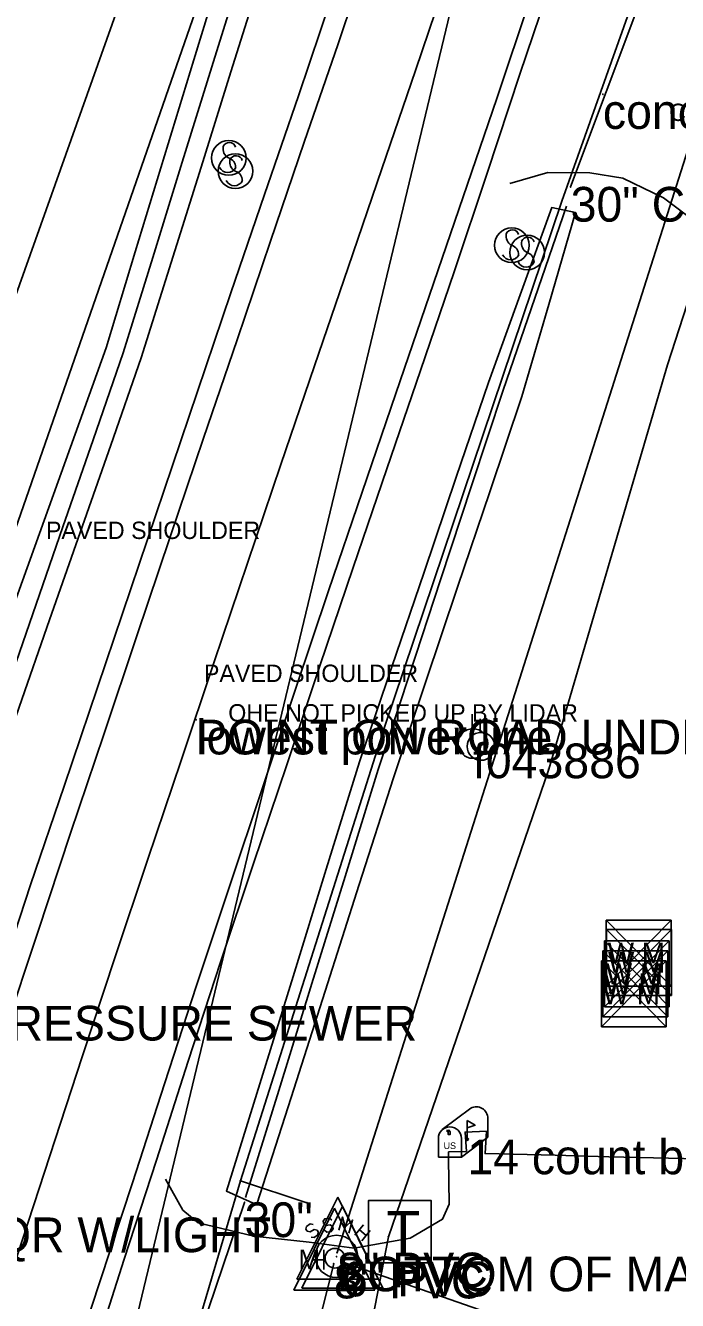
# Model space of a CAD drawing. Extents: x 1802180 to 1804859, y 572524 to 575172.
# Drawn here: x 1803260.9 to 1803354.8, y 573167.1 to 573350.8 of the extents above; entities that cross this region are included whole.
import ezdxf

# ---------------------------------------------------------------- set-up
doc = ezdxf.new("R2010")
doc.units = 0
for name, color, linetype in [('EX_EDGE_PAVEMENT', 7, 'Continuous'), ('EX_SHOULDER', 7, 'Continuous'), ('S_BASELINE', 7, 'Continuous'), ('S_CAL_CORNER', 7, 'Continuous'), ('S_DITCHLINE', 7, 'Continuous'), ('S_DRG_PT_SYM', 7, 'Continuous'), ('S_ELECTRIC_UTILITIES_ANNOT', 7, 'Continuous'), ('S_GAS_UTILITIES', 7, 'Continuous'), ('S_MAILBOX', 7, 'Continuous'), ('S_MAILBOX_ANNOT', 7, 'Continuous'), ('S_MANHOLE', 7, 'Continuous'), ('S_MANHOLE_ANNOT', 7, 'Continuous'), ('S_MISC_BOUNDARY', 7, 'Continuous'), ('S_MSC_PT_SYM', 7, 'Continuous'), ('S_PARKING', 7, 'Continuous'), ('S_PARKING_ANNOT', 7, 'Continuous'), ('S_PAVEMENT_CROWN', 7, 'Continuous'), ('S_SANITARY_SEWER', 7, 'Continuous'), ('S_SANITARY_SEWER_ANNOT', 7, 'Continuous'), ('S_SHOULDER_ANNOT', 7, 'Continuous'), ('S_SIDE_DRAIN', 7, 'Continuous'), ('S_SIDE_DRAIN_ANNOT', 7, 'Continuous'), ('S_SIGN', 7, 'Continuous'), ('S_SURVEY_TEXT', 7, 'Continuous'), ('S_SURVEY_TEXT_ANNOT', 7, 'Continuous'), ('S_TELEPHONE_UTILITIES', 7, 'Continuous'), ('S_UTILITY_POLE', 7, 'Continuous'), ('S_UTILITY_POLE_ANNOT', 7, 'Continuous'), ('S_UTL_PT_SYM', 7, 'Continuous'), ('S_WATER_UTILITIES', 7, 'Continuous')]:
    doc.layers.add(name, color=color, linetype=linetype)

msp = doc.modelspace()

# ---------------------------------------------------------------- linework, layer by layer
at = {"layer": 'EX_EDGE_PAVEMENT'}
for points in [[(1803243.97, 573162.84), (1803248.63, 573177.34), (1803253.31, 573191.59), (1803257.97, 573205.83), (1803262.69, 573220.17), (1803267.44, 573234.4), (1803272.21, 573248.61), (1803276.97, 573262.83), (1803281.77, 573277.1), (1803286.59, 573291.3), (1803291.41, 573305.51), (1803296.22, 573319.72), (1803301.07, 573333.96), (1803305.94, 573348.15), (1803310.67, 573362.21)], [(1803333.6, 573354.66), (1803328.79, 573340.27), (1803323.93, 573326.08), (1803319.1, 573311.94), (1803314.25, 573297.74), (1803309.42, 573283.54), (1803304.58, 573269.34), (1803299.82, 573255.17), (1803295.08, 573240.94), (1803290.3, 573226.71), (1803285.55, 573212.49), (1803280.96, 573198.31), (1803276.36, 573184.02), (1803271.65, 573169.78), (1803267.02, 573155.77)]]:
    msp.add_lwpolyline(points, dxfattribs=at)
at = {"layer": 'EX_SHOULDER'}
for points in [[(1803244.54, 573072.71), (1803248.63, 573087.13), (1803252.74, 573101.56), (1803256.68, 573116.02), (1803261.13, 573130.33), (1803265.55, 573144.67), (1803270.59, 573158.74), (1803275.14, 573173.03), (1803279.82, 573187.3), (1803284.37, 573201.59), (1803289.02, 573215.83), (1803293.78, 573230.06), (1803298.55, 573244.28), (1803303.32, 573258.5), (1803308.12, 573272.7), (1803312.96, 573286.9), (1803317.8, 573301.09), (1803322.64, 573315.29), (1803327.4, 573329.51), (1803332.12, 573343.77), (1803336.9, 573357.97)], [(1803217.45, 573083.45), (1803221.29, 573098), (1803225.36, 573112.47), (1803229.64, 573126.91), (1803234.04, 573141.25), (1803238.37, 573155.6), (1803242.85, 573169.96), (1803247.56, 573184.22), (1803252.29, 573198.46), (1803256.96, 573212.72), (1803261.68, 573226.97), (1803266.49, 573241.18), (1803271.3, 573255.39), (1803276.08, 573269.61), (1803280.88, 573283.83), (1803285.7, 573298.03), (1803290.52, 573312.24), (1803295.34, 573326.45), (1803300.24, 573340.63), (1803305.01, 573354.83)]]:
    msp.add_lwpolyline(points, dxfattribs=at)
at = {"layer": 'S_BASELINE'}
msp.add_line((1803248.92, 573048.02), (1803445.92, 573868.28), dxfattribs=at)
at = {"layer": 'S_CAL_CORNER'}
for p, q in [((1803305.42, 573180.37), (1803299.55, 573168.56)), ((1803305.89, 573181.96), (1803300.01, 573170.14)), ((1803306.6, 573180.67), (1803300.72, 573168.85)), ((1803305.42, 573180.37), (1803311.23, 573168.56)), ((1803305.89, 573181.96), (1803311.7, 573170.14)), ((1803306.6, 573180.67), (1803312.41, 573168.85)), ((1803300.01, 573170.14), (1803311.7, 573170.14)), ((1803299.55, 573168.56), (1803311.23, 573168.56)), ((1803300.72, 573168.85), (1803312.41, 573168.85))]:
    msp.add_line(p, q, dxfattribs=at)
at = {"layer": 'S_DITCHLINE'}
for points in [[(1803289.39, 573359.67), (1803285.18, 573345.84), (1803280.96, 573332.01), (1803276.75, 573318.18), (1803272.53, 573304.35), (1803268.08, 573291.91), (1803263.63, 573279.47), (1803259.18, 573267.02), (1803254.72, 573254.58), (1803250.18, 573241.12), (1803245.65, 573227.66), (1803241.11, 573214.21), (1803236.57, 573200.75), (1803232.01, 573188.55), (1803227.46, 573176.35), (1803222.91, 573164.14), (1803218.36, 573151.94), (1803215.97, 573139.2), (1803213.59, 573126.47), (1803211.2, 573113.73), (1803208.82, 573100.99)], [(1803292.03, 573358.57), (1803287.77, 573344.83), (1803283.51, 573331.09), (1803279.25, 573317.35), (1803274.99, 573303.61), (1803270.66, 573291.08), (1803266.33, 573278.54), (1803262, 573266.01), (1803257.67, 573253.48), (1803253.07, 573240.14), (1803248.46, 573226.8), (1803243.85, 573213.46), (1803239.24, 573200.12), (1803234.76, 573187.94), (1803230.29, 573175.75), (1803225.81, 573163.57)], [(1803294.83, 573357.82), (1803290.52, 573344.09), (1803286.21, 573330.36), (1803281.9, 573316.63), (1803277.59, 573302.9), (1803273.2, 573290.32), (1803268.8, 573277.73), (1803264.41, 573265.15), (1803260.01, 573252.56), (1803255.39, 573239.11), (1803250.78, 573225.66), (1803246.16, 573212.21), (1803241.54, 573198.76), (1803237.14, 573186.74), (1803232.74, 573174.73), (1803228.35, 573162.72), (1803223.95, 573150.71), (1803220.17, 573138.28), (1803216.38, 573125.85), (1803212.6, 573113.42), (1803208.82, 573100.99)], [(1803294.14, 573180.94), (1803289.87, 573182.85), (1803294.67, 573198.31), (1803299.46, 573213.78), (1803304.25, 573229.24), (1803309.04, 573244.7), (1803313.68, 573258.36), (1803318.32, 573272.03), (1803322.96, 573285.7), (1803327.6, 573299.36), (1803332.16, 573311.95), (1803336.72, 573324.54), (1803340.13, 573323.82), (1803336.27, 573310.57), (1803332.41, 573297.33), (1803327.79, 573283.59), (1803323.16, 573269.85), (1803318.54, 573256.12), (1803313.92, 573242.38), (1803309, 573227.02), (1803304.08, 573211.67), (1803299.17, 573196.32), (1803294.25, 573180.96)], [(1803292.63, 573181.91), (1803297.4, 573197.34), (1803302.17, 573212.76), (1803306.94, 573228.19), (1803311.71, 573243.61), (1803316.21, 573257.27), (1803320.7, 573270.93), (1803325.19, 573284.59), (1803329.69, 573298.25), (1803334.26, 573311.49), (1803338.83, 573324.73)]]:
    msp.add_lwpolyline(points, dxfattribs=at)
at = {"layer": 'S_DRG_PT_SYM'}
for points in [[(1803339.43, 573327.52), (1803339.43, 573327.57), (1803339.43, 573327.52), (1803339.38, 573327.52), (1803339.43, 573327.52), (1803339.43, 573327.47), (1803339.43, 573327.52), (1803339.48, 573327.52)], [(1803292.48, 573181.22), (1803292.48, 573181.27), (1803292.48, 573181.22), (1803292.43, 573181.22), (1803292.48, 573181.22), (1803292.48, 573181.17), (1803292.48, 573181.22), (1803292.53, 573181.22)]]:
    msp.add_lwpolyline(points, dxfattribs=at)
at = {"layer": 'S_GAS_UTILITIES'}
for p, q in [((1803338.18, 573325.46), (1803351.16, 573362.17)), ((1803312.58, 573249.52), (1803338.18, 573325.46)), ((1803291.88, 573184.33), (1803312.58, 573249.52)), ((1803282.01, 573151.05), (1803291.88, 573184.33)), ((1803291.88, 573184.33), (1803301.46, 573181.17))]:
    msp.add_line(p, q, dxfattribs=at)
at = {"layer": 'S_MAILBOX'}
for p, q in [((1803320.93, 573191.71), (1803325.07, 573194.82)), ((1803327.5, 573193.34), (1803327.5, 573190.63)), ((1803324.55, 573193), (1803324.55, 573190.28)), ((1803320.38, 573190.43), (1803320.38, 573187.72)), ((1803323.7, 573187.72), (1803327.5, 573190.63)), ((1803323.7, 573190.43), (1803323.7, 573187.72)), ((1803320.38, 573187.72), (1803323.7, 573187.72))]:
    msp.add_line(p, q, dxfattribs=at)
for points in [[(1803321.56, 573191.55), (1803321.79, 573191.41), (1803321.79, 573191.02), (1803322.09, 573191.02), (1803322.09, 573191.38), (1803321.9, 573191.63), (1803321.56, 573191.58)], [(1803324.55, 573193), (1803325.66, 573192.33), (1803324.55, 573191.98)]]:
    msp.add_lwpolyline(points, dxfattribs=at)
for centre, end in [((1803325.84, 573193.34), 117.5718), ((1803322.04, 573190.43), 180)]:
    msp.add_arc(centre, 1.66, 0, end, dxfattribs=at)
msp.add_ellipse((1803324.55, 573190.28), major_axis=(0.145, 0.132), ratio=0.564646, dxfattribs=at)
at = {"layer": 'S_MANHOLE'}
for p, q in [((1803303.91, 573171.57), (1803303.91, 573174.4)), ((1803302.33, 573172.97), (1803303.91, 573172.97))]:
    msp.add_line(p, q, dxfattribs=at)
msp.add_circle((1803305.49, 573173.18), 1.42, dxfattribs=at)
at = {"layer": 'S_MISC_BOUNDARY'}
msp.add_lwpolyline([(1802880.88, 573735.6), (1803051.71, 573733.48), (1803213.27, 573730.83), (1803216.46, 573532.09), (1803301.63, 573530.07), (1803296.75, 573432.28), (1803274.96, 573355.36), (1803226.68, 573219.53), (1803202.19, 573137.5), (1803157.77, 572977.33), (1803158.5, 572726.69), (1802889.88, 572728.1)], dxfattribs=at)
at = {"layer": 'S_MSC_PT_SYM'}
for points in [[(1803344.07, 573340.88), (1803344.07, 573340.93), (1803344.07, 573340.88), (1803344.02, 573340.88), (1803344.07, 573340.88), (1803344.07, 573340.83), (1803344.07, 573340.88), (1803344.12, 573340.88)], [(1803285.51, 573250.76), (1803285.51, 573250.81), (1803285.51, 573250.76), (1803285.46, 573250.76), (1803285.51, 573250.76), (1803285.51, 573250.71), (1803285.51, 573250.76), (1803285.56, 573250.76)]]:
    msp.add_lwpolyline(points, dxfattribs=at)
at = {"layer": 'S_PARKING'}
for points in [[(1803330.66, 573328), (1803336.13, 573329.59), (1803342.17, 573329.57), (1803346.94, 573328.79), (1803352.78, 573325.97), (1803358.03, 573322.02), (1803360.17, 573317.79), (1803360.25, 573312.38), (1803359.47, 573303.06), (1803363.42, 573302.55), (1803374.67, 573302.5), (1803389.66, 573302.32), (1803393.51, 573302.29), (1803394.36, 573302.26), (1803394.42, 573298.33)], [(1803330.66, 573328), (1803336.13, 573329.59), (1803342.17, 573329.57), (1803346.94, 573328.79), (1803352.78, 573325.97), (1803358.03, 573322.02), (1803360.17, 573317.79), (1803360.25, 573312.38), (1803359.47, 573303.06), (1803363.42, 573302.55), (1803374.67, 573302.5), (1803389.66, 573302.32), (1803393.51, 573302.29), (1803394.36, 573302.26), (1803394.42, 573298.33)], [(1803327.12, 573188.25), (1803327.29, 573191.47), (1803324.24, 573191.35), (1803324.43, 573188.57), (1803321.86, 573188.49), (1803321.82, 573187.57), (1803321.95, 573180.95), (1803320.98, 573178.8), (1803316.31, 573176.08), (1803308.26, 573174.62), (1803301.77, 573175.5), (1803293.82, 573176.37), (1803285.78, 573178.27), (1803283.61, 573180.11), (1803281.09, 573184.58)], [(1803359.95, 573187.45), (1803344.95, 573187.8), (1803337.21, 573188.04), (1803327.12, 573188.25), (1803327.29, 573191.47), (1803324.24, 573191.35), (1803324.43, 573188.57), (1803321.86, 573188.49), (1803321.82, 573187.57), (1803321.95, 573180.95), (1803320.98, 573178.8), (1803316.31, 573176.08), (1803308.26, 573174.62), (1803301.77, 573175.5), (1803293.82, 573176.37), (1803285.78, 573178.27), (1803283.61, 573180.11), (1803281.09, 573184.58)], [(1803359.95, 573187.45), (1803344.95, 573187.8), (1803337.21, 573188.04), (1803327.12, 573188.25)]]:
    msp.add_lwpolyline(points, dxfattribs=at)
at = {"layer": 'S_PAVEMENT_CROWN'}
msp.add_lwpolyline([(1803255.16, 573159.41), (1803259.77, 573173.68), (1803264.45, 573187.93), (1803269.12, 573202.19), (1803273.79, 573216.44), (1803278.57, 573230.66), (1803283.35, 573244.88), (1803288.11, 573259.1), (1803292.89, 573273.32), (1803297.72, 573287.52), (1803302.55, 573301.72), (1803307.38, 573315.92), (1803312.22, 573330.12), (1803317.11, 573344.3), (1803321.91, 573358.51)], dxfattribs=at)
at = {"layer": 'S_SANITARY_SEWER'}
for p, q in [((1803305.8, 573173.98), (1803414.87, 573517.25)), ((1803290.35, 573367.12), (1803235.59, 573209.54)), ((1803301.4, 573177.74), (1803301.32, 573177.35)), ((1803301.32, 573177.35), (1803301.51, 573177.08)), ((1803301.94, 573178.13), (1803301.4, 573177.74)), ((1803301.51, 573177.08), (1803301.94, 573176.97)), ((1803302.36, 573178.05), (1803301.94, 573178.13)), ((1803301.94, 573176.97), (1803302.48, 573177.32)), ((1803302.48, 573177.32), (1803302.95, 573177.24)), ((1803302.95, 573177.24), (1803303.1, 573176.97)), ((1803303.1, 573176.97), (1803303.02, 573176.54)), ((1803308.37, 573176.5), (1803309.61, 573177.97)), ((1803309.03, 573177.28), (1803310, 573176.46)), ((1803310.58, 573177.16), (1803309.34, 573175.69)), ((1803302.48, 573176.15), (1803302.09, 573176.23)), ((1803303.02, 573176.54), (1803302.48, 573176.15)), ((1803253.84, 572969.86), (1803305.33, 573172.39)), ((1803306.51, 573172.68), (1803354.58, 573155.92))]:
    msp.add_line(p, q, dxfattribs=at)
for points in [[(1803305.04, 573178.67), (1803304.69, 573178.94), (1803304.03, 573178.87), (1803303.8, 573178.52), (1803303.84, 573178.21), (1803304.19, 573177.9), (1803304.81, 573178.01), (1803305.19, 573177.7), (1803305.23, 573177.39), (1803304.96, 573177.01), (1803304.34, 573176.93), (1803303.99, 573177.2)], [(1803307.48, 573176.81), (1803308.02, 573178.67), (1803306.98, 573177.66), (1803306.59, 573179.1), (1803306.05, 573177.24)]]:
    msp.add_lwpolyline(points, dxfattribs=at)
msp.add_circle((1803305.72, 573173.44), 3.05, dxfattribs=at)
at = {"layer": 'S_SIDE_DRAIN'}
for p, q in [((1803339.43, 573327.52), (1803350.15, 573356.19)), ((1803282.63, 573152.15), (1803292.48, 573181.22))]:
    msp.add_line(p, q, dxfattribs=at)
at = {"layer": 'S_SIGN'}
for centre in [(1803290.2, 573331.69), (1803291.16, 573329.79), (1803330.96, 573319.11), (1803333.17, 573318.07)]:
    msp.add_circle(centre, 2.5, dxfattribs=at)
for centre, radius, start, end in [((1803290.89, 573333.02), 1.51, 167.1196, 241.9813), ((1803290.28, 573332.96), 0.952, 16.5258, 156.8957), ((1803289.79, 573330.35), 1.4, 358.6529, 73.7063), ((1803291.85, 573331.12), 1.51, 167.1196, 241.9813), ((1803291.24, 573331.06), 0.952, 16.5258, 156.8957), ((1803290.05, 573330.87), 1.28, 204.641, 335.359), ((1803290.75, 573328.45), 1.4, 358.6529, 73.7063), ((1803291.01, 573328.97), 1.28, 204.641, 335.359), ((1803331.64, 573320.44), 1.51, 167.1196, 241.9813), ((1803331.03, 573320.38), 0.952, 16.5258, 156.8957), ((1803333.25, 573319.34), 0.952, 16.5258, 156.8957), ((1803330.54, 573317.76), 1.4, 358.6529, 73.7063), ((1803333.86, 573319.4), 1.51, 167.1196, 241.9813), ((1803330.8, 573318.28), 1.28, 204.641, 335.359), ((1803333.02, 573317.24), 1.28, 204.641, 335.359), ((1803332.76, 573316.72), 1.4, 358.6529, 73.7063)]:
    msp.add_arc(centre, radius, start, end, dxfattribs=at)
at = {"layer": 'S_SURVEY_TEXT'}
msp.add_line((1803290.13, 573250.5), (1803290.13, 573250.5), dxfattribs=at)
at = {"layer": 'S_TELEPHONE_UTILITIES'}
msp.add_lwpolyline([(1803310.33, 573172.5), (1803310.33, 573181.5), (1803319.33, 573181.5), (1803319.33, 573172.5)], close=True, dxfattribs=at)
at = {"layer": 'S_UTILITY_POLE'}
for p, q in [((1803325.24, 573249.47), (1803325.24, 573251.58)), ((1803326.4, 573248.92), (1803326.4, 573250.91))]:
    msp.add_line(p, q, dxfattribs=at)
for centre, radius in [((1803325.36, 573247.33), 2.13), ((1803326.52, 573246.91), 2)]:
    msp.add_circle(centre, radius, dxfattribs=at)
at = {"layer": 'S_UTL_PT_SYM'}
for points in [[(1803338.18, 573325.46), (1803338.18, 573325.51), (1803338.18, 573325.46), (1803338.13, 573325.46), (1803338.18, 573325.46), (1803338.18, 573325.41), (1803338.18, 573325.46), (1803338.23, 573325.46)], [(1803353.38, 573301.89), (1803353.38, 573301.94), (1803353.38, 573301.89), (1803353.33, 573301.89), (1803353.38, 573301.89), (1803353.38, 573301.84), (1803353.38, 573301.89), (1803353.43, 573301.89)], [(1803285.51, 573250.76), (1803285.51, 573250.81), (1803285.51, 573250.76), (1803285.46, 573250.76), (1803285.51, 573250.76), (1803285.51, 573250.71), (1803285.51, 573250.76), (1803285.56, 573250.76)], [(1803312.58, 573249.52), (1803312.58, 573249.57), (1803312.58, 573249.52), (1803312.53, 573249.52), (1803312.58, 573249.52), (1803312.58, 573249.47), (1803312.58, 573249.52), (1803312.63, 573249.52)], [(1803336.27, 573243.65), (1803336.27, 573243.7), (1803336.27, 573243.65), (1803336.22, 573243.65), (1803336.27, 573243.65), (1803336.27, 573243.6), (1803336.27, 573243.65), (1803336.32, 573243.65)], [(1803291.88, 573184.33), (1803291.88, 573184.38), (1803291.88, 573184.33), (1803291.83, 573184.33), (1803291.88, 573184.33), (1803291.88, 573184.28), (1803291.88, 573184.33), (1803291.93, 573184.33)], [(1803291.88, 573184.33), (1803291.88, 573184.38), (1803291.88, 573184.33), (1803291.83, 573184.33), (1803291.88, 573184.33), (1803291.88, 573184.28), (1803291.88, 573184.33), (1803291.93, 573184.33)], [(1803301.46, 573181.17), (1803301.46, 573181.22), (1803301.46, 573181.17), (1803301.41, 573181.17), (1803301.46, 573181.17), (1803301.46, 573181.12), (1803301.46, 573181.17), (1803301.51, 573181.17)], [(1803313.18, 573176.27), (1803313.18, 573176.32), (1803313.18, 573176.27), (1803313.13, 573176.27), (1803313.18, 573176.27), (1803313.18, 573176.22), (1803313.18, 573176.27), (1803313.23, 573176.27)], [(1803305.73, 573173.41), (1803305.73, 573173.46), (1803305.73, 573173.41), (1803305.68, 573173.41), (1803305.73, 573173.41), (1803305.73, 573173.36), (1803305.73, 573173.41), (1803305.78, 573173.41)], [(1803305.8, 573173.98), (1803305.8, 573174.03), (1803305.8, 573173.98), (1803305.75, 573173.98), (1803305.8, 573173.98), (1803305.8, 573173.93), (1803305.8, 573173.98), (1803305.85, 573173.98)], [(1803305.33, 573172.39), (1803305.33, 573172.44), (1803305.33, 573172.39), (1803305.28, 573172.39), (1803305.33, 573172.39), (1803305.33, 573172.34), (1803305.33, 573172.39), (1803305.38, 573172.39)], [(1803306.51, 573172.68), (1803306.51, 573172.73), (1803306.51, 573172.68), (1803306.46, 573172.68), (1803306.51, 573172.68), (1803306.51, 573172.63), (1803306.51, 573172.68), (1803306.56, 573172.68)]]:
    msp.add_lwpolyline(points, dxfattribs=at)
at = {"layer": 'S_WATER_UTILITIES'}
for p, q in [((1803353.38, 573301.89), (1803399.02, 573443.59)), ((1803336.27, 573243.65), (1803353.38, 573301.89)), ((1803313.18, 573176.27), (1803336.27, 573243.65)), ((1803344.56, 573221.88), (1803353.9, 573221.88)), ((1803344.56, 573221.88), (1803344.56, 573212.38)), ((1803344.56, 573221.88), (1803353.9, 573212.38)), ((1803353.9, 573221.88), (1803344.56, 573212.38)), ((1803353.9, 573221.88), (1803353.9, 573212.38)), ((1803344.6, 573220.53), (1803353.94, 573220.53)), ((1803344.6, 573220.53), (1803344.6, 573211.04)), ((1803344.6, 573220.53), (1803353.94, 573211.04)), ((1803353.94, 573220.53), (1803344.6, 573211.04)), ((1803353.94, 573220.53), (1803353.94, 573211.04)), ((1803344.08, 573217.44), (1803353.42, 573217.44)), ((1803344.08, 573217.44), (1803344.08, 573207.95)), ((1803344.08, 573217.44), (1803353.42, 573207.95)), ((1803353.42, 573217.44), (1803344.08, 573207.95)), ((1803344.3, 573218.9), (1803353.63, 573218.9)), ((1803344.3, 573218.9), (1803344.3, 573209.4)), ((1803344.3, 573218.9), (1803353.63, 573209.4)), ((1803353.63, 573218.9), (1803344.3, 573209.4)), ((1803353.42, 573217.44), (1803353.42, 573207.95)), ((1803353.63, 573218.9), (1803353.63, 573209.4)), ((1803343.86, 573216.01), (1803353.2, 573216.01)), ((1803343.86, 573216.01), (1803343.86, 573206.51)), ((1803343.86, 573216.01), (1803353.2, 573206.51)), ((1803353.2, 573216.01), (1803343.86, 573206.51)), ((1803353.2, 573216.01), (1803353.2, 573206.51)), ((1803344.56, 573212.38), (1803353.9, 573212.38)), ((1803344.6, 573211.04), (1803353.94, 573211.04)), ((1803344.08, 573207.95), (1803353.42, 573207.95)), ((1803344.3, 573209.4), (1803353.63, 573209.4)), ((1803343.86, 573206.51), (1803353.2, 573206.51)), ((1803301.21, 573114.11), (1803313.18, 573176.27))]:
    msp.add_line(p, q, dxfattribs=at)

# ---------------------------------------------------------------- texts
at = {"layer": 'S_ELECTRIC_UTILITIES_ANNOT'}
msp.add_text('lowest power line ', height=5, dxfattribs=at).set_placement((1803285.51, 573245.76))
at = {"layer": 'S_MAILBOX'}
msp.add_text('US', height=0.96, rotation=360, dxfattribs=at).set_placement((1803321.14, 573188.91))
at = {"layer": 'S_MAILBOX_ANNOT'}
msp.add_text("14 count black metal for' apt c", height=5, dxfattribs=at).set_placement((1803324.55, 573185.28))
at = {"layer": 'S_MANHOLE'}
msp.add_text('M', height=2.82, dxfattribs=at).set_placement((1803300.24, 573171.6))
at = {"layer": 'S_MANHOLE_ANNOT'}
msp.add_text('BOTTOM OF MANHOLE', height=5, dxfattribs=at).set_placement((1803305.73, 573168.41))
at = {"layer": 'S_PARKING_ANNOT'}
msp.add_text('CONC PARKING', height=2.5, dxfattribs=at).set_placement((1803353.62, 573337.02))
at = {"layer": 'S_SANITARY_SEWER_ANNOT'}
for s, p in [('HIGH PRESSURE SEWER  ', (1803235.59, 573204.54)), ('8" PVC', (1803305.8, 573168.98)), ('8" PVC     ', (1803305.33, 573167.39)), ('6" PVC', (1803306.51, 573167.68))]:
    msp.add_text(s, height=5, dxfattribs=at).set_placement(p)
at = {"layer": 'S_SHOULDER_ANNOT'}
for p in [(1803263.88, 573276.8), (1803286.63, 573256.2)]:
    msp.add_text('PAVED SHOULDER', height=2.5, dxfattribs=at).set_placement(p)
at = {"layer": 'S_SIDE_DRAIN_ANNOT'}
for s, p in [('30" CMP', (1803339.43, 573322.52)), ('30"       ', (1803292.48, 573176.22))]:
    msp.add_text(s, height=5, dxfattribs=at).set_placement(p)
at = {"layer": 'S_SURVEY_TEXT_ANNOT'}
for s, height, p in [('concrete dw', 5, (1803344.07, 573335.88)), ('OHE NOT PICKED UP BY LIDAR', 2.5, (1803290.13, 573250.5)), ('POINT ON ROAD UNDER LOWEST LINE ', 5, (1803285.51, 573245.76))]:
    msp.add_text(s, height=height, dxfattribs=at).set_placement(p)
at = {"layer": 'S_TELEPHONE_UTILITIES'}
msp.add_text('T', height=6, rotation=360, dxfattribs=at).set_placement((1803312.9, 573174))
at = {"layer": 'S_UTILITY_POLE_ANNOT'}
for s, p in [('f043886', (1803325.36, 573242.33)), ('14596W 60QR W/LIGHT', (1803222.33, 573174.05))]:
    msp.add_text(s, height=5, dxfattribs=at).set_placement(p)
at = {"layer": 'S_WATER_UTILITIES'}
for p in [(1803344.77, 573215.64), (1803344.81, 573214.3), (1803344.5, 573212.66), (1803344.28, 573211.21), (1803344.06, 573209.77)]:
    msp.add_text('W M', height=3, rotation=360, dxfattribs=at).set_placement(p)

doc.saveas('drawing.dxf')
